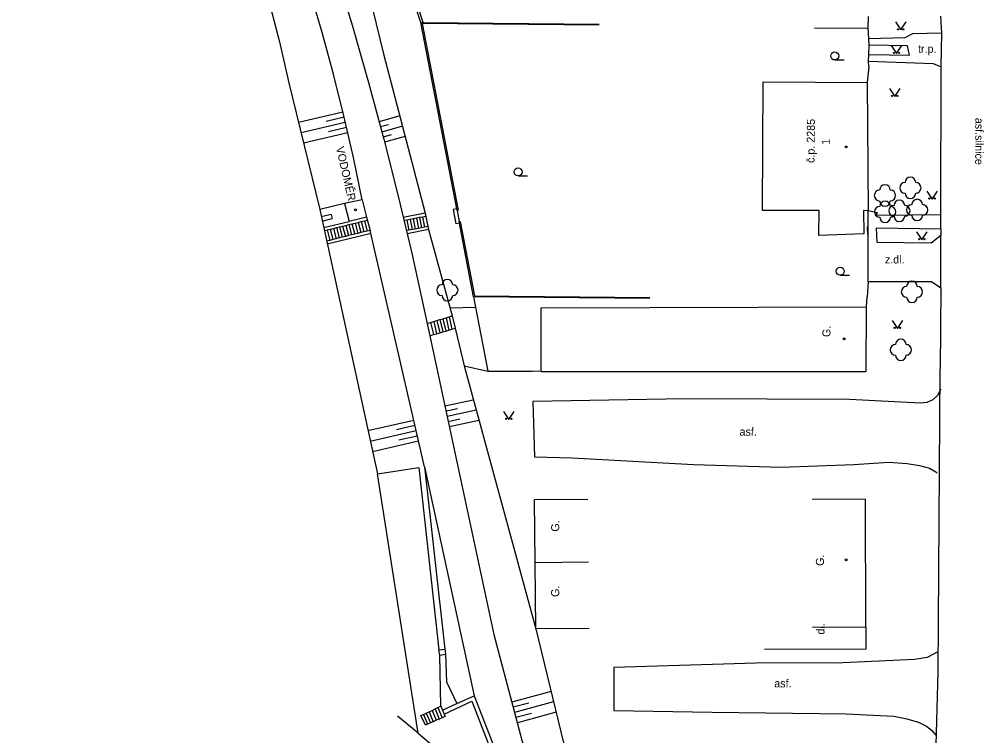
# Model space of a CAD drawing. Extents: x -584400 to -581602, y -1210894 to -1208793.
# Drawn here: x -582931.4 to -582841, y -1210317.6 to -1210250.4 of the extents above; entities that cross this region are included whole.
import ezdxf

# ---------------------------------------------------------------- set-up
doc = ezdxf.new("R2010")
doc.units = 0
for name, color, linetype in [('BUDOVY_MĚŘ', 7, 'Continuous'), ('BUDOVY_NEMĚŘ', 7, 'Continuous'), ('POMOC_POPIS', 7, 'Continuous'), ('ROZHRANÍ_PLOCH', 7, 'Continuous'), ('VÝŠKOPIS', 7, 'Continuous'), ('ZELEŇ', 7, 'Continuous'), ('ZN_BUDOV', 7, 'Continuous'), ('ZN_DOPLŇKOVÉ', 7, 'Continuous'), ('ZN_KULTUR', 7, 'Continuous'), ('Č_POPIS_EVID', 7, 'Continuous'), ('Č_POPIS_ORIENT', 7, 'Continuous')]:
    doc.layers.add(name, color=color, linetype=linetype)

msp = doc.modelspace()

# ---------------------------------------------------------------- linework, layer by layer
at = {"layer": 'BUDOVY_MĚŘ'}
for points in [[(-582851.9, -1210256.36), (-582851.81, -1210268.4), (-582852.26, -1210268.34)], [(-582899.26, -1210267.34), (-582900.89, -1210267.71), (-582900.48, -1210269.37)], [(-582899.26, -1210267.34), (-582898.83, -1210268.97), (-582900.48, -1210269.37)], [(-582852.26, -1210268.34), (-582852.22, -1210270.54)], [(-582851.99, -1210283.43), (-582851.98, -1210277.38)], [(-582882.47, -1210283.43), (-582851.99, -1210283.43)], [(-582878.09, -1210295.43), (-582883.09, -1210295.49)], [(-582883.02, -1210301.39), (-582883.09, -1210295.49)], [(-582852.03, -1210307.41), (-582852.07, -1210295.42), (-582857.07, -1210295.44)], [(-582878.02, -1210301.33), (-582883.02, -1210301.39)], [(-582877.97, -1210307.52), (-582882.97, -1210307.56), (-582883.02, -1210301.39)], [(-582852.03, -1210307.41), (-582857.03, -1210307.43)]]:
    msp.add_lwpolyline(points, dxfattribs=at)
at = {"layer": 'BUDOVY_NEMĚŘ'}
for points in [[(-582852.22, -1210270.54), (-582856.43, -1210270.71), (-582856.42, -1210268.36), (-582857.87, -1210268.36), (-582861.72, -1210268.35), (-582861.66, -1210256.3), (-582851.9, -1210256.36)], [(-582882.47, -1210283.43), (-582882.46, -1210277.47), (-582851.98, -1210277.38)]]:
    msp.add_lwpolyline(points, dxfattribs=at)
at = {"layer": 'ROZHRANÍ_PLOCH'}
for points in [[(-582899.26, -1210267.34), (-582900.07, -1210263.4), (-582900.97, -1210259.47), (-582901.95, -1210255.56), (-582903, -1210251.67), (-582904.13, -1210247.81), (-582905.33, -1210243.96), (-582906.62, -1210240.14), (-582908.18, -1210235.79), (-582909.77, -1210232.25), (-582911.42, -1210228.75), (-582913.15, -1210225.28), (-582914.96, -1210221.85), (-582916.83, -1210218.45), (-582918.77, -1210215.1), (-582921.58, -1210210.51), (-582924.15, -1210207.3), (-582926.78, -1210204.14), (-582929.47, -1210201.03), (-582931.39, -1210198.89)], [(-582901.76, -1210245.81), (-582900.17, -1210251.08), (-582898.66, -1210256.37), (-582897.23, -1210261.68), (-582895.88, -1210267.01), (-582894.6, -1210272.36), (-582892.9, -1210280.09)], [(-582845.01, -1210268.77), (-582844.96, -1210254.88), (-582844.92, -1210251.72), (-582845.02, -1210250.13)], [(-582844.92, -1210251.72), (-582847.65, -1210251.78), (-582848.38, -1210252.18), (-582851.75, -1210252.25)], [(-582851.75, -1210253.74), (-582847.93, -1210253.79), (-582848.14, -1210252.92), (-582851.73, -1210252.87)], [(-582851.8, -1210254.37), (-582845.71, -1210254.57), (-582844.96, -1210254.88)], [(-582900.89, -1210267.71), (-582903.23, -1210268.27)], [(-582890.37, -1210268.19), (-582890.71, -1210268.25), (-582890.48, -1210269.6)], [(-582890.34, -1210268.34), (-582890.16, -1210269.4)], [(-582845.01, -1210268.77), (-582851.11, -1210268.83), (-582850.94, -1210268.56), (-582851.81, -1210268.4)], [(-582902.15, -1210268.72), (-582903.08, -1210268.94)], [(-582903, -1210269.34), (-582902.05, -1210269.11)], [(-582902.15, -1210268.72), (-582902.05, -1210269.11)], [(-582899.04, -1210269.33), (-582898.75, -1210269.26)], [(-582898.83, -1210268.97), (-582898.5, -1210270.22)], [(-582893.34, -1210268.61), (-582895.39, -1210269.01)], [(-582895.05, -1210269.25), (-582895.32, -1210269.3)], [(-582894.76, -1210269.2), (-582895.05, -1210269.25)], [(-582895.05, -1210269.25), (-582894.87, -1210270.2)], [(-582894.46, -1210269.14), (-582894.76, -1210269.2)], [(-582894.76, -1210269.2), (-582894.57, -1210270.14)], [(-582894.17, -1210269.08), (-582894.46, -1210269.14)], [(-582894.46, -1210269.14), (-582894.28, -1210270.09)], [(-582893.87, -1210269.02), (-582894.17, -1210269.08)], [(-582894.17, -1210269.08), (-582893.98, -1210270.03)], [(-582893.58, -1210268.97), (-582893.87, -1210269.02)], [(-582893.87, -1210269.02), (-582893.69, -1210269.97)], [(-582893.28, -1210268.91), (-582893.58, -1210268.97)], [(-582893.58, -1210268.97), (-582893.4, -1210269.91)], [(-582893.34, -1210268.61), (-582893.28, -1210268.91)], [(-582893.28, -1210268.91), (-582893.1, -1210269.85)], [(-582845.02, -1210270.07), (-582845.01, -1210268.77)], [(-582902.86, -1210269.95), (-582900.48, -1210269.37)], [(-582902.79, -1210270.24), (-582902.54, -1210270.18)], [(-582902.54, -1210270.18), (-582902.25, -1210270.11)], [(-582902.54, -1210270.18), (-582902.28, -1210271.15)], [(-582902.25, -1210270.11), (-582901.95, -1210270.03)], [(-582902.25, -1210270.11), (-582901.99, -1210271.08)], [(-582901.95, -1210270.03), (-582901.66, -1210269.96)], [(-582901.95, -1210270.03), (-582901.7, -1210271)], [(-582901.66, -1210269.96), (-582901.37, -1210269.89)], [(-582901.66, -1210269.96), (-582901.41, -1210270.93)], [(-582901.37, -1210269.89), (-582901.08, -1210269.82)], [(-582901.37, -1210269.89), (-582901.12, -1210270.86)], [(-582901.08, -1210269.82), (-582900.79, -1210269.75)], [(-582901.08, -1210269.82), (-582900.82, -1210270.78)], [(-582900.79, -1210269.75), (-582900.5, -1210269.68)], [(-582900.79, -1210269.75), (-582900.53, -1210270.71)], [(-582900.5, -1210269.68), (-582900.21, -1210269.61)], [(-582900.5, -1210269.68), (-582900.24, -1210270.64)], [(-582900.21, -1210269.61), (-582899.92, -1210269.54)], [(-582900.21, -1210269.61), (-582899.95, -1210270.57)], [(-582899.92, -1210269.54), (-582899.62, -1210269.47)], [(-582899.92, -1210269.54), (-582899.66, -1210270.5)], [(-582899.62, -1210269.47), (-582899.33, -1210269.4)], [(-582899.62, -1210269.47), (-582899.37, -1210270.43)], [(-582899.33, -1210269.4), (-582899.04, -1210269.33)], [(-582899.33, -1210269.4), (-582899.08, -1210270.36)], [(-582899.04, -1210269.33), (-582898.79, -1210270.29)], [(-582898.5, -1210270.22), (-582898.79, -1210270.29)], [(-582893.41, -1210292.37), (-582898.5, -1210270.22)], [(-582894.87, -1210270.2), (-582895.1, -1210270.24)], [(-582893.04, -1210270.15), (-582895.03, -1210270.53)], [(-582894.57, -1210270.14), (-582894.87, -1210270.2)], [(-582894.28, -1210270.09), (-582894.57, -1210270.14)], [(-582893.98, -1210270.03), (-582894.28, -1210270.09)], [(-582893.69, -1210269.97), (-582893.98, -1210270.03)], [(-582893.4, -1210269.91), (-582893.69, -1210269.97)], [(-582893.1, -1210269.85), (-582893.4, -1210269.91)], [(-582893.1, -1210269.85), (-582893.04, -1210270.15)], [(-582890.13, -1210269.54), (-582890.48, -1210269.6)], [(-582845.02, -1210270.71), (-582845.91, -1210271.42), (-582850.97, -1210271.36), (-582851.02, -1210269.97), (-582845.02, -1210270.07), (-582845.02, -1210270.71)], [(-582898.42, -1210270.51), (-582902.52, -1210271.52)], [(-582901.99, -1210271.08), (-582902.28, -1210271.15)], [(-582901.7, -1210271), (-582901.99, -1210271.08)], [(-582901.41, -1210270.93), (-582901.7, -1210271)], [(-582901.12, -1210270.86), (-582901.41, -1210270.93)], [(-582900.82, -1210270.78), (-582901.12, -1210270.86)], [(-582900.53, -1210270.71), (-582900.82, -1210270.78)], [(-582900.24, -1210270.64), (-582900.53, -1210270.71)], [(-582899.95, -1210270.57), (-582900.24, -1210270.64)], [(-582899.66, -1210270.5), (-582899.95, -1210270.57)], [(-582899.37, -1210270.43), (-582899.66, -1210270.5)], [(-582899.08, -1210270.36), (-582899.37, -1210270.43)], [(-582898.79, -1210270.29), (-582899.08, -1210270.36)], [(-582845.02, -1210275.59), (-582845.02, -1210270.71)], [(-582902.28, -1210271.15), (-582902.58, -1210271.23)], [(-582851.82, -1210275.01), (-582845.87, -1210275), (-582845.02, -1210275.59), (-582845.06, -1210283.18)], [(-582891.03, -1210277.47), (-582888.61, -1210277.43)], [(-582891.39, -1210278.41), (-582891.1, -1210278.33)], [(-582891.1, -1210278.33), (-582890.81, -1210278.24)], [(-582891.1, -1210278.33), (-582890.83, -1210279.48)], [(-582890.81, -1210278.24), (-582890.54, -1210279.39)], [(-582893.15, -1210278.93), (-582892.83, -1210278.84)], [(-582892.83, -1210278.84), (-582892.54, -1210278.75)], [(-582892.83, -1210278.84), (-582892.56, -1210279.99)], [(-582892.54, -1210278.75), (-582892.26, -1210278.67)], [(-582892.54, -1210278.75), (-582892.27, -1210279.9)], [(-582892.26, -1210278.67), (-582891.97, -1210278.58)], [(-582892.26, -1210278.67), (-582891.98, -1210279.82)], [(-582891.97, -1210278.58), (-582891.68, -1210278.5)], [(-582891.97, -1210278.58), (-582891.69, -1210279.73)], [(-582891.68, -1210278.5), (-582891.39, -1210278.41)], [(-582891.68, -1210278.5), (-582891.4, -1210279.65)], [(-582891.39, -1210278.41), (-582891.12, -1210279.57)], [(-582892.9, -1210280.09), (-582892.56, -1210279.99)], [(-582892.9, -1210280.09), (-582886.92, -1210308.11), (-582883.86, -1210319.53)], [(-582892.56, -1210279.99), (-582892.27, -1210279.9)], [(-582892.27, -1210279.9), (-582891.98, -1210279.82)], [(-582891.98, -1210279.82), (-582891.69, -1210279.73)], [(-582891.69, -1210279.73), (-582891.4, -1210279.65)], [(-582891.4, -1210279.65), (-582891.12, -1210279.57)], [(-582891.12, -1210279.57), (-582890.83, -1210279.48)], [(-582890.83, -1210279.48), (-582890.54, -1210279.39)], [(-582889.7, -1210282.91), (-582887.46, -1210283.4)], [(-582845.92, -1210335.56), (-582845.27, -1210311.63), (-582845.06, -1210283.18)], [(-582845, -1210285.09), (-582845.31, -1210285.7), (-582845.74, -1210286.09), (-582846.33, -1210286.35), (-582846.95, -1210286.41), (-582853.56, -1210286.07), (-582869, -1210286), (-582883.25, -1210286.25), (-582883.1, -1210291.43), (-582879.56, -1210291.53), (-582868.18, -1210292.17), (-582859.98, -1210292.42), (-582853.17, -1210292.17), (-582849.89, -1210291.95), (-582848.17, -1210292.06), (-582847.02, -1210292.27), (-582846.08, -1210292.5), (-582845.47, -1210292.86), (-582845.36, -1210292.96)], [(-582897.82, -1210293.04), (-582893.95, -1210292.43), (-582892.05, -1210309.54)], [(-582893.41, -1210292.37), (-582888.76, -1210313.84)], [(-582893.41, -1210292.37), (-582891.51, -1210309.46)], [(-582852.03, -1210307.41), (-582852.04, -1210309.47), (-582861.52, -1210309.5)], [(-582892.05, -1210309.54), (-582891.51, -1210309.46)], [(-582891.98, -1210310.03), (-582892.05, -1210309.54)], [(-582891.98, -1210310.03), (-582891.44, -1210309.95)], [(-582891.51, -1210309.46), (-582891.44, -1210309.95)], [(-582891.44, -1210309.95), (-582891.33, -1210312.53), (-582890.37, -1210314.58)], [(-582845.28, -1210309.73), (-582846.29, -1210310.24), (-582847.47, -1210310.44), (-582854.84, -1210310.78), (-582861.28, -1210310.74), (-582875.67, -1210311.2), (-582875.67, -1210315.21), (-582866.45, -1210315.38), (-582853.87, -1210315.53), (-582849.4, -1210315.75), (-582848.33, -1210315.98), (-582847.1, -1210316.3), (-582846.35, -1210316.68), (-582845.84, -1210317.1), (-582845.43, -1210317.57)], [(-582891.88, -1210314.83), (-582891.98, -1210310.03)], [(-582891.57, -1210315.56), (-582888.97, -1210314.36), (-582887.09, -1210319.18)], [(-582890.37, -1210314.58), (-582888.76, -1210313.84)], [(-582888.76, -1210313.84), (-582886.67, -1210319.21)], [(-582893.24, -1210315.46), (-582892.97, -1210315.34)], [(-582892.97, -1210315.34), (-582892.69, -1210315.21)], [(-582892.97, -1210315.34), (-582892.58, -1210316.27)], [(-582892.69, -1210315.21), (-582892.42, -1210315.08)], [(-582892.69, -1210315.21), (-582892.3, -1210316.14)], [(-582892.42, -1210315.08), (-582892.15, -1210314.95)], [(-582892.42, -1210315.08), (-582892.03, -1210316.02)], [(-582892.15, -1210314.95), (-582891.88, -1210314.83)], [(-582892.15, -1210314.95), (-582891.76, -1210315.9)], [(-582891.88, -1210314.83), (-582891.72, -1210315.2)], [(-582891.72, -1210315.2), (-582890.37, -1210314.58)], [(-582891.72, -1210315.2), (-582891.57, -1210315.56)], [(-582894, -1210317.36), (-582895.94, -1210315.76)], [(-582893.13, -1210316.51), (-582893.32, -1210316.6), (-582893.74, -1210315.69), (-582893.51, -1210315.59)], [(-582893.51, -1210315.59), (-582893.24, -1210315.46)], [(-582893.51, -1210315.59), (-582893.13, -1210316.51)], [(-582893.24, -1210315.46), (-582892.85, -1210316.39)], [(-582892.58, -1210316.27), (-582892.85, -1210316.39)], [(-582892.3, -1210316.14), (-582892.58, -1210316.27)], [(-582892.03, -1210316.02), (-582892.3, -1210316.14)], [(-582891.76, -1210315.9), (-582892.03, -1210316.02)], [(-582891.57, -1210315.56), (-582891.48, -1210315.77), (-582891.76, -1210315.9)], [(-582892.85, -1210316.39), (-582893.13, -1210316.51)]]:
    msp.add_lwpolyline(points, dxfattribs=at)
at = {"layer": 'VÝŠKOPIS'}
for points in [[(-582917.26, -1210224.44), (-582915.82, -1210227.44), (-582914.46, -1210230.48), (-582913.17, -1210233.55), (-582911.95, -1210236.65), (-582910.81, -1210239.78), (-582909.75, -1210242.93), (-582908.76, -1210246.11), (-582907.84, -1210249.32), (-582907.01, -1210252.54), (-582906.14, -1210256.26)], [(-582899.34, -1210245.08), (-582897.25, -1210253.67), (-582893.34, -1210268.61)], [(-582906.14, -1210256.26), (-582903.23, -1210268.27)], [(-582905.22, -1210260.07), (-582901.06, -1210259.09)], [(-582904.98, -1210261.04), (-582900.83, -1210260.07)], [(-582902.62, -1210259.97), (-582900.94, -1210259.58)], [(-582895.72, -1210259.49), (-582897.67, -1210260.03)], [(-582904.75, -1210262.01), (-582900.6, -1210261.04)], [(-582902.39, -1210260.95), (-582900.72, -1210260.55)], [(-582896.79, -1210260.31), (-582897.54, -1210260.51)], [(-582895.47, -1210260.46), (-582897.41, -1210261)], [(-582896.53, -1210261.27), (-582897.28, -1210261.48)], [(-582895.22, -1210261.43), (-582897.16, -1210261.96)], [(-582903.23, -1210268.27), (-582897.82, -1210293.04)], [(-582893.04, -1210270.15), (-582890.81, -1210278.24)], [(-582890.54, -1210279.39), (-582889.7, -1210282.91)], [(-582889.7, -1210282.91), (-582882.97, -1210307.56), (-582880.08, -1210319.4)], [(-582888.83, -1210286.12), (-582891.49, -1210286.68)], [(-582890.31, -1210286.94), (-582891.39, -1210287.17)], [(-582888.57, -1210287.08), (-582891.28, -1210287.66)], [(-582898.71, -1210288.99), (-582894.41, -1210288)], [(-582890.08, -1210287.92), (-582891.18, -1210288.15)], [(-582888.3, -1210288.05), (-582891.07, -1210288.64)], [(-582898.5, -1210289.97), (-582894.19, -1210288.98)], [(-582896.02, -1210288.89), (-582894.3, -1210288.49)], [(-582898.28, -1210290.94), (-582893.96, -1210289.95)], [(-582895.8, -1210289.86), (-582894.08, -1210289.47)], [(-582894, -1210317.36), (-582897.82, -1210293.04)], [(-582881.53, -1210313.45), (-582885.22, -1210314.44)], [(-582883.62, -1210314.52), (-582885.09, -1210314.92)], [(-582881.3, -1210314.42), (-582884.96, -1210315.4)], [(-582881.06, -1210315.39), (-582884.7, -1210316.37)], [(-582883.37, -1210315.49), (-582884.83, -1210315.88)], [(-582894, -1210317.36), (-582891.88, -1210319.17)]]:
    msp.add_lwpolyline(points, dxfattribs=at)
at = {"layer": 'ZELEŇ'}
for centre in [(-582847.86, -1210266.23), (-582850.24, -1210266.94), (-582848.89, -1210268.38), (-582847.22, -1210268.3), (-582850.23, -1210268.48), (-582891.26, -1210275.82), (-582847.71, -1210275.98), (-582848.76, -1210281.41)]:
    msp.add_circle(centre, 0.0005, dxfattribs=at)
for centre, start, end in [((-582847.86, -1210265.73), 0, 179.99999), ((-582850.74, -1210266.94), 89.99999, 269.99999), ((-582850.24, -1210266.44), 0, 179.99999), ((-582849.74, -1210266.94), 270, 89.99999), ((-582848.36, -1210266.23), 89.99999, 269.99999), ((-582847.36, -1210266.23), 270, 89.99999), ((-582850.24, -1210267.44), 179.99999, 359.99999), ((-582850.23, -1210267.98), 0, 179.99999), ((-582848.89, -1210267.88), 0, 179.99999), ((-582847.86, -1210266.73), 179.99999, 359.99999), ((-582847.22, -1210267.8), 0, 179.99999), ((-582850.73, -1210268.48), 89.99999, 269.99999), ((-582849.39, -1210268.38), 89.99999, 269.99999), ((-582849.73, -1210268.48), 270, 89.99999), ((-582848.39, -1210268.38), 270, 89.99999), ((-582847.72, -1210268.3), 89.99999, 269.99999), ((-582846.72, -1210268.3), 270, 89.99999), ((-582850.23, -1210268.98), 179.99999, 359.99999), ((-582848.89, -1210268.88), 179.99999, 359.99999), ((-582847.22, -1210268.8), 179.99999, 359.99999), ((-582891.76, -1210275.82), 89.99999, 269.99999), ((-582891.26, -1210275.32), 0, 179.99999), ((-582890.76, -1210275.82), 270, 89.99999), ((-582848.21, -1210275.98), 89.99999, 269.99999), ((-582847.71, -1210275.48), 0, 179.99999), ((-582847.21, -1210275.98), 270, 89.99999), ((-582891.26, -1210276.32), 179.99999, 359.99999), ((-582847.71, -1210276.48), 179.99999, 359.99999), ((-582849.26, -1210281.41), 89.99999, 269.99999), ((-582848.76, -1210280.91), 0, 179.99999), ((-582848.26, -1210281.41), 270, 89.99999), ((-582848.76, -1210281.91), 179.99999, 359.99999)]:
    msp.add_arc(centre, 0.5, start, end, dxfattribs=at)
at = {"layer": 'ZN_BUDOV'}
for centre in [(-582853.87, -1210262.4), (-582899.87, -1210268.29), (-582854.08, -1210280.39), (-582853.87, -1210301.09)]:
    msp.add_circle(centre, 0.0875, dxfattribs=at)
at = {"layer": 'ZN_DOPLŇKOVÉ'}
for points in [[(-582893.75, -1210250.72), (-582895.86, -1210244.25), (-582895.67, -1210244.19)], [(-582893.54, -1210250.72), (-582895.67, -1210244.19)], [(-582851.81, -1210251.27), (-582851.8, -1210250.18)], [(-582890.34, -1210268.34), (-582893.75, -1210250.72), (-582893.54, -1210250.72)], [(-582877.03, -1210250.98), (-582893.63, -1210250.82), (-582890.24, -1210268.32)], [(-582893.54, -1210250.72), (-582877.03, -1210250.88)], [(-582856.85, -1210251.23), (-582851.81, -1210251.27)], [(-582851.76, -1210254.86), (-582851.8, -1210254.37), (-582851.75, -1210253.74), (-582851.73, -1210252.87), (-582851.75, -1210252.25), (-582851.81, -1210251.27)], [(-582851.76, -1210254.86), (-582851.9, -1210256.36)], [(-582890.34, -1210268.34), (-582890.24, -1210268.32)], [(-582851.82, -1210275.01), (-582851.81, -1210268.4)], [(-582872.27, -1210276.61), (-582888.8, -1210276.45), (-582890.16, -1210269.4), (-582890.06, -1210269.38)], [(-582890.06, -1210269.38), (-582888.72, -1210276.35), (-582872.27, -1210276.51)], [(-582851.92, -1210269.87), (-582851.87, -1210270.59)], [(-582851.82, -1210275.01), (-582851.92, -1210276.45)], [(-582888.8, -1210276.45), (-582887.46, -1210283.4)], [(-582851.98, -1210277.38), (-582851.92, -1210276.45)], [(-582887.46, -1210283.4), (-582886.03, -1210283.41)], [(-582886.03, -1210283.41), (-582883.31, -1210283.42)], [(-582882.47, -1210283.43), (-582883.31, -1210283.42)]]:
    msp.add_lwpolyline(points, dxfattribs=at)
at = {"layer": 'ZN_KULTUR'}
for p, q in [((-582854.95, -1210254.245), (-582854.075, -1210254.245)), ((-582884.63, -1210265.115), (-582883.755, -1210265.115)), ((-582854.44, -1210274.425), (-582853.565, -1210274.425))]:
    msp.add_line(p, q, dxfattribs=at)
for points in [[(-582849.27, -1210250.68), (-582848.77, -1210251.43), (-582848.27, -1210250.68)], [(-582849.66, -1210252.88), (-582849.16, -1210253.63), (-582848.66, -1210252.88)], [(-582849.83, -1210256.91), (-582849.33, -1210257.66), (-582848.83, -1210256.91)], [(-582846.33, -1210266.53), (-582845.83, -1210267.28), (-582845.33, -1210266.53)], [(-582847.28, -1210270.34), (-582846.78, -1210271.09), (-582846.28, -1210270.34)], [(-582849.58, -1210278.65), (-582849.08, -1210279.4), (-582848.58, -1210278.65)], [(-582885.99, -1210287.18), (-582885.49, -1210287.93), (-582884.99, -1210287.18)]]:
    msp.add_lwpolyline(points, dxfattribs=at)
for centre, radius in [((-582849.02, -1210251.38), 0.05), ((-582848.52, -1210251.38), 0.05), ((-582854.95, -1210253.87), 0.375), ((-582849.41, -1210253.58), 0.05), ((-582848.91, -1210253.58), 0.05), ((-582849.58, -1210257.61), 0.05), ((-582849.08, -1210257.61), 0.05), ((-582884.63, -1210264.74), 0.375), ((-582846.08, -1210267.23), 0.05), ((-582845.58, -1210267.23), 0.05), ((-582847.03, -1210271.04), 0.05), ((-582846.53, -1210271.04), 0.05), ((-582854.44, -1210274.05), 0.375), ((-582849.33, -1210279.35), 0.05), ((-582848.83, -1210279.35), 0.05), ((-582885.74, -1210287.88), 0.05), ((-582885.24, -1210287.88), 0.05)]:
    msp.add_circle(centre, radius, dxfattribs=at)

# ---------------------------------------------------------------- texts
at = {"layer": 'POMOC_POPIS'}
msp.add_text('tr.p.', height=0.75, dxfattribs=at).set_placement((-582847.14, -1210253.57))
for s, rotation, p in [('asf.silnice', 269.79374, (-582841.77, -1210259.67)), ('VODOMĚR', 282.91842, (-582901.71, -1210262.46)), ('z.dl.', 0.09631, (-582850.25, -1210273.32)), ('G.', 88.99089, (-582855.36, -1210280.22)), ('asf.', 359.89977, (-582863.87, -1210289.46)), ('G.', 89.99998, (-582880.78, -1210298.46)), ('G.', 88.99089, (-582855.97, -1210301.67)), ('G.', 89.99998, (-582880.78, -1210304.58)), ('dl.', 89.69333, (-582855.91, -1210308.1)), ('asf.', 359.89977, (-582860.62, -1210313.05))]:
    msp.add_text(s, height=0.75, rotation=rotation, dxfattribs=at).set_placement(p)
at = {"layer": 'Č_POPIS_EVID'}
msp.add_text('1', height=0.75, rotation=89.79927, dxfattribs=at).set_placement((-582855.42, -1210262.2))
at = {"layer": 'Č_POPIS_ORIENT'}
msp.add_text('č.p. 2285', height=0.75, rotation=89.35002, dxfattribs=at).set_placement((-582856.85, -1210263.9))

doc.saveas('drawing.dxf')
